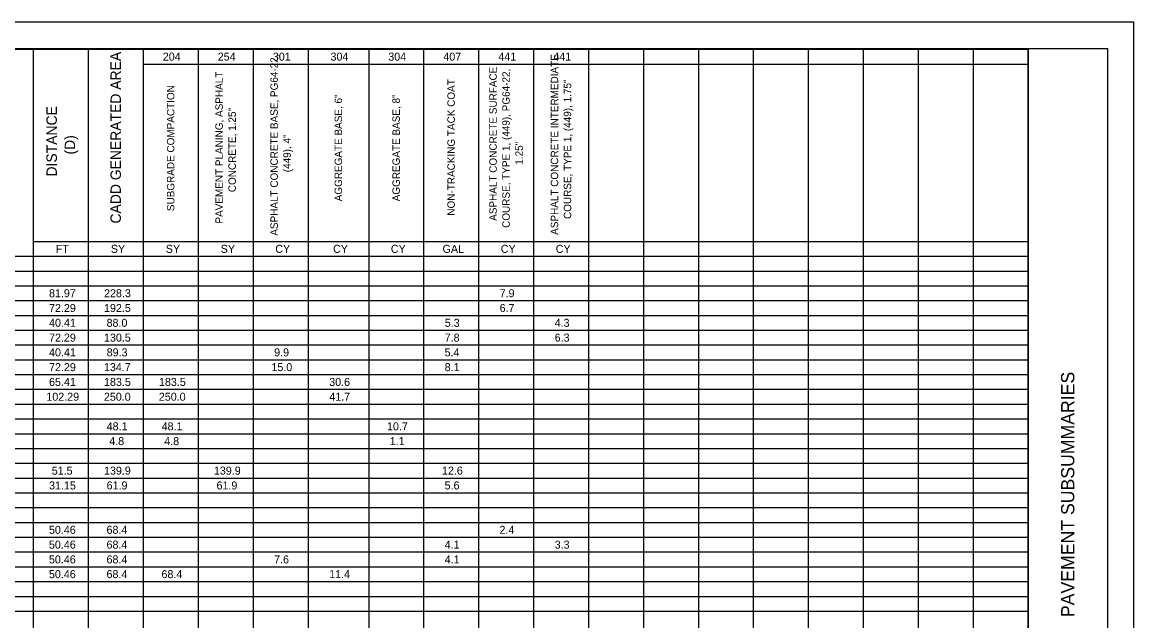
# Model space of a CAD drawing. Extents: x 0 to 34, y 0 to 22.
# Drawn here: x 12.96 to 34, y 10.67 to 22 of the extents above; entities that cross this region are included whole.
import ezdxf

# ---------------------------------------------------------------- set-up
doc = ezdxf.new("R2010")
doc.units = 0
for name, color, linetype in [('SH_Border', 7, 'Continuous'), ('SH_Cut_Line', 7, 'Continuous'), ('SH_Data', 7, 'Continuous'), ('SH_Text', 7, 'Continuous')]:
    doc.layers.add(name, color=color, linetype=linetype)

msp = doc.modelspace()

# ---------------------------------------------------------------- linework, layer by layer
at = {"layer": 'SH_Border'}
msp.add_line((32, 0.5), (32, 21.5), dxfattribs=at)
msp.add_lwpolyline([(1.5, 21.5), (33.5, 21.5), (33.5, 0.5), (1.5, 0.5)], close=True, dxfattribs=at)
at = {"layer": 'SH_Cut_Line'}
msp.add_lwpolyline([(0, 0), (34, 0), (34, 22), (0, 22)], close=True, dxfattribs=at)
at = {"layer": 'SH_Text'}
for p, q in [((1.5, 21.488), (32, 21.488)), ((13.171, 21.488), (13.171, 1.058)), ((14.211, 21.488), (14.211, 1.058)), ((15.251, 21.488), (15.251, 0.499)), ((16.291, 21.488), (16.291, 0.499)), ((17.331, 21.488), (17.331, 0.499)), ((18.371, 21.488), (18.371, 0.499)), ((19.519, 21.488), (19.519, 0.778)), ((20.559, 21.488), (20.559, 0.499)), ((21.599, 21.488), (21.599, 0.499)), ((22.639, 21.488), (22.639, 0.499)), ((23.679, 21.488), (23.679, 0.499)), ((24.719, 21.488), (24.719, 0.499)), ((25.759, 21.488), (25.759, 0.499)), ((26.799, 21.488), (26.799, 0.499)), ((27.84, 21.488), (27.84, 0.499)), ((28.88, 21.488), (28.88, 0.499)), ((29.92, 21.488), (29.92, 0.499)), ((30.96, 21.488), (30.96, 0.499)), ((32, 21.488), (32, 0.499)), ((15.251, 21.209), (32, 21.209)), ((13.171, 17.85), (32, 17.85)), ((1.5, 17.57), (32, 17.57)), ((1.5, 17.291), (32, 17.291)), ((1.5, 17.011), (32, 17.011)), ((1.5, 16.731), (32, 16.731)), ((1.5, 16.451), (32, 16.451)), ((1.5, 16.171), (32, 16.171)), ((1.5, 15.891), (32, 15.891)), ((1.5, 15.611), (32, 15.611)), ((1.5, 15.331), (32, 15.331)), ((1.5, 15.052), (32, 15.052)), ((1.5, 14.772), (32, 14.772)), ((1.5, 14.492), (32, 14.492)), ((1.5, 14.212), (32, 14.212)), ((1.5, 13.932), (32, 13.932)), ((1.5, 13.652), (32, 13.652)), ((1.5, 13.372), (32, 13.372)), ((1.5, 13.093), (32, 13.093)), ((1.5, 12.813), (32, 12.813)), ((1.5, 12.533), (32, 12.533)), ((1.5, 12.253), (32, 12.253)), ((1.5, 11.973), (32, 11.973)), ((1.5, 11.693), (32, 11.693)), ((1.5, 11.413), (32, 11.413)), ((1.5, 11.133), (32, 11.133)), ((1.5, 10.854), (32, 10.854))]:
    msp.add_line(p, q, dxfattribs=at)

# ---------------------------------------------------------------- texts
at = {"layer": 'SH_Data'}
msp.add_text('PAVEMENT SUBSUMMARIES', height=0.25, rotation=90, dxfattribs=at).set_placement((32.875, 10.741))
at = {"layer": 'SH_Text'}
for s, height, p in [('CADD GENERATED AREA', 0.19701, (14.829, 18.19)), ('ASPHALT CONCRETE BASE, PG64-22, ', 0.14072, (17.799, 17.96)), ('ASPHALT CONCRETE INTERMEDIATE ', 0.14072, (23.106, 17.976)), ('PAVEMENT PLANING, ASPHALT ', 0.14072, (16.758, 18.189)), ('ASPHALT CONCRETE SURFACE ', 0.14072, (21.943, 18.241)), ('COURSE, TYPE 1, (449), PG64-22, ', 0.14072, (22.189, 18.108)), ('NON-TRACKING TACK COAT', 0.14072, (21.149, 18.339)), ('COURSE, TYPE 1, (449), 1.75"', 0.14072, (23.352, 18.276)), ('SUBGRADE COMPACTION', 0.14072, (15.841, 18.425)), ('AGGREGATE BASE, 6"', 0.14072, (19.015, 18.611)), ('AGGREGATE BASE, 8"', 0.14072, (20.109, 18.611)), ('DISTANCE ', 0.197, (13.617, 19.08)), ('CONCRETE, 1.25"', 0.14072, (17.005, 18.784)), ('(D)', 0.197, (13.962, 19.496)), ('(449), 4"', 0.1407, (18.045, 19.161)), ('1.25"', 0.1407, (22.435, 19.304))]:
    msp.add_text(s, height=height, rotation=90, dxfattribs=at).set_placement(p)
for s, p in [('204', (15.622, 21.273)), ('254', (16.662, 21.273)), ('301', (17.705, 21.273)), ('304', (18.796, 21.273)), ('304', (19.89, 21.273)), ('407', (20.932, 21.273)), ('441', (21.973, 21.273)), ('441', (23.013, 21.273)), ('FT', (13.597, 17.635)), ('SY', (14.639, 17.635)), ('SY', (15.679, 17.635)), ('SY', (16.719, 17.635)), ('CY', (17.751, 17.635)), ('CY', (18.845, 17.635)), ('CY', (19.938, 17.635)), ('GAL', (20.917, 17.635)), ('CY', (22.019, 17.635)), ('CY', (23.059, 17.635)), ('81.97', (13.468, 16.795)), ('228.3', (14.51, 16.795)), ('7.9', (21.998, 16.795)), ('72.29', (13.469, 16.515)), ('192.5', (14.509, 16.515)), ('6.7', (21.997, 16.515)), ('40.41', (13.469, 16.235)), ('88.0', (14.558, 16.235)), ('5.3', (20.959, 16.235)), ('4.3', (23.039, 16.235)), ('72.29', (13.469, 15.955)), ('130.5', (14.509, 15.955)), ('7.8', (20.957, 15.955)), ('6.3', (23.039, 15.955)), ('40.41', (13.469, 15.676)), ('89.3', (14.56, 15.676)), ('9.9', (17.73, 15.676)), ('5.4', (20.955, 15.676)), ('72.29', (13.469, 15.396)), ('134.7', (14.508, 15.396)), ('15.0', (17.678, 15.396)), ('8.1', (20.958, 15.396)), ('65.41', (13.469, 15.116)), ('183.5', (14.509, 15.116)), ('183.5', (15.55, 15.116)), ('30.6', (18.772, 15.116)), ('102.29', (13.418, 14.836)), ('250.0', (14.507, 14.836)), ('250.0', (15.547, 14.836)), ('41.7', (18.773, 14.836)), ('48.1', (14.56, 14.276)), ('48.1', (15.6, 14.276)), ('10.7', (19.866, 14.276)), ('4.8', (14.609, 13.996)), ('4.8', (15.649, 13.996)), ('1.1', (19.918, 13.996)), ('51.5', (13.52, 13.437)), ('139.9', (14.509, 13.437)), ('139.9', (16.589, 13.437)), ('12.6', (20.906, 13.437)), ('31.15', (13.469, 13.157)), ('61.9', (14.559, 13.157)), ('61.9', (16.639, 13.157)), ('5.6', (20.956, 13.157)), ('50.46', (13.467, 12.317)), ('68.4', (14.557, 12.317)), ('2.4', (21.995, 12.317)), ('50.46', (13.467, 12.037)), ('68.4', (14.557, 12.037)), ('4.1', (20.958, 12.037)), ('3.3', (23.039, 12.037)), ('50.46', (13.467, 11.757)), ('68.4', (14.557, 11.757)), ('7.6', (17.729, 11.757)), ('4.1', (20.958, 11.757)), ('50.46', (13.467, 11.478)), ('68.4', (14.557, 11.478)), ('68.4', (15.597, 11.478)), ('11.4', (18.771, 11.478))]:
    msp.add_text(s, height=0.1515, dxfattribs=at).set_placement(p)

doc.saveas('drawing.dxf')
